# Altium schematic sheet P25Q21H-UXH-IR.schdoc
size 127 x 101 mm
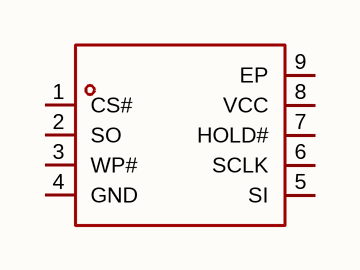
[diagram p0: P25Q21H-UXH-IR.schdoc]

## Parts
U?  p25q21h-uxh-ir  [USON-8_L3.0-W2.0-P0.50-BL-EP-1]  (value not drawn)

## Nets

Not connected (* = marked no-connect by the designer): U? 1(CS#) 2(SO) 3(WP#) 4(GND) 5(SI) 6(SCLK) 7(HOLD#) 8(VCC) 9(EP)

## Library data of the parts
U? = p25q21h-uxh-ir: 接口类型:SPI;存储容量:2Mbit;时钟频率(fc):104MHz;; Manufacturer: PUYA(普冉); AddInBom: yes; Interface: SPI; Memory Size: 2Mbit; Clock Frequency: 104MHz; Voltage - Supply: 2.3V~3.6V; Standby Supply Current: 9uA; Program / Erase Cycles: 100000次; Write Cycle Time (tWC): 8ms; Page Programming Time (Tpp): 2ms; Block Erase Time(tBE): 8ms@(32KB); Data Retention - TDR (Year): 20年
